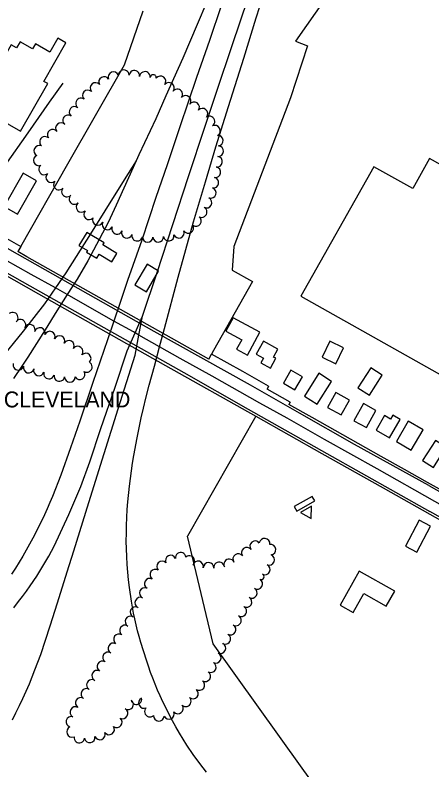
# Model space of a CAD drawing. Extents: x -25029 to 2274964, y -81170 to 687028.
# Drawn here: x -16160 to -15374, y -63645 to -62222 of the extents above; entities that cross this region are included whole.
import ezdxf

# ---------------------------------------------------------------- set-up
doc = ezdxf.new("R2010")
doc.units = 0
for name, color, linetype in [('81911BEA - RW_X_Fee_RW', 7, 'Continuous'), ('BLDG', 7, 'Continuous'), ('CITY-NAME', 7, 'Continuous'), ('GE_X_CL_2000', 7, 'Continuous'), ('ROAD', 7, 'Continuous'), ('TRANSPWRLN', 7, 'Continuous'), ('TREES', 7, 'Continuous')]:
    doc.layers.add(name, color=color, linetype=linetype)

msp = doc.modelspace()

# ---------------------------------------------------------------- linework, layer by layer
at = {"layer": '81911BEA - RW_X_Fee_RW'}
for p, q in [((-15533.2, -62131.6), (-15631, -62271.5)), ((-15954, -62316), (-15918.9, -62214.6)), ((-15631, -62271.5), (-15608.5, -62280.5)), ((-15608.5, -62280.5), (-15640.6, -62378.1)), ((-15640.6, -62378.1), (-15747.6, -62658.6)), ((-16251.2, -62601.3), (-16149.6, -62658.5)), ((-16149.6, -62658.5), (-16155.1, -62668.2)), ((-15747.6, -62658.6), (-15750.9, -62702.9)), ((-16138.1, -62677.7), (-16155.1, -62668.2)), ((-15794.9, -62870.8), (-16138.1, -62677.7)), ((-15750.9, -62702.9), (-15712.5, -62724.4)), ((-15794.9, -62870.8), (-15789.5, -62861.2)), ((-15730.7, -62894.3), (-15789.5, -62861.2)), ((-15681.9, -62921.8), (-15684.8, -62927)), ((-15641.3, -62951.5), (-15684.8, -62927)), ((-15641.3, -62951.5), (-15643.7, -62955.9)), ((-15705.9, -62978.3), (-15835.1, -63204)), ((-15786.7, -63407.4), (-15835.1, -63204))]:
    msp.add_line(p, q, dxfattribs=at)
for points in [[(-16149.6, -62658.5), (-16060.5, -62502.6), (-15954, -62316)], [(-16840.1, -62340.1), (-16798.4, -62363.6), (-16741.8, -62395.4), (-16693.9, -62422.4), (-16645.9, -62449.4), (-16562.7, -62496.2), (-16514.5, -62523.3), (-16429.4, -62571.2), (-16398.8, -62588.4), (-16342.2, -62620.3), (-16307.3, -62639.9), (-16115.8, -62747.6), (-15876.3, -62882.4), (-15705.9, -62978.3)], [(-15712.5, -62724.4), (-15785.7, -62854.4), (-15789.5, -62861.2)], [(-15681.9, -62921.8), (-15691.2, -62916.5), (-15730.7, -62894.3)], [(-15333.3, -63130.6), (-15336.9, -63128.5), (-15382.3, -63103), (-15425.8, -63078.5), (-15469.4, -63054), (-15513, -63029.5), (-15556.6, -63004.9), (-15600.1, -62980.4), (-15643.7, -62955.9)], [(-15705.9, -62978.3), (-15581.3, -63048.4), (-15466.1, -63113.2), (-15353.4, -63176.6), (-15200.7, -63262.5), (-15148.4, -63292), (-15118.6, -63308.8), (-15061.3, -63341), (-15017.3, -63365.7), (-14973.7, -63390.3), (-14930.2, -63414.8), (-14879.6, -63443.2)], [(-15569, -63710.4), (-15570.4, -63708.5), (-15618.7, -63641.2), (-15786.7, -63407.4)]]:
    msp.add_lwpolyline(points, dxfattribs=at)
at = {"layer": 'BLDG'}
for points in [[(-16079.7, -62265.9), (-16094.8, -62292.3), (-16122, -62276.7), (-16127.3, -62286.1), (-16150.7, -62272.7), (-16157.4, -62284.3), (-16167.7, -62278.4), (-16233.5, -62393.4), (-16149.9, -62441.3), (-16098.5, -62351.6), (-16106.1, -62347.3), (-16064.5, -62274.6)], [(-15142.5, -62703.9), (-15122.1, -62715.4), (-15082, -62644.2), (-15171.4, -62594), (-15209.8, -62662.3), (-15310.5, -62605.7), (-15278.5, -62548.8), (-15378.2, -62492.8), (-15410.1, -62549.5), (-15483.8, -62508.1), (-15621, -62752.3), (-15278, -62945)], [(-16145, -62520.5), (-16180.9, -62583.4), (-16155.5, -62597.8), (-16119.7, -62535)], [(-16039.8, -62656.5), (-16023.5, -62666.2), (-16025.4, -62669.4), (-16006.2, -62680.7), (-16001.7, -62673.1), (-15977.5, -62687.5), (-15968, -62671.4), (-15994.7, -62655.6), (-15992.2, -62651.4), (-16025.2, -62631.9)], [(-15934.1, -62730.8), (-15912.2, -62743.6), (-15889.4, -62704.7), (-15911.3, -62691.9)], [(-15762.6, -62817.9), (-15732.7, -62834.1), (-15742.3, -62851.9), (-15721.6, -62863), (-15698.4, -62820), (-15749, -62792.7)], [(-15705.2, -62861.2), (-15691.7, -62868.7), (-15696.7, -62877.7), (-15678.6, -62887.7), (-15668.4, -62869.1), (-15672.6, -62866.8), (-15664.4, -62852.1), (-15691.8, -62837)], [(-15540.7, -62849.7), (-15566.6, -62837.1), (-15581.1, -62867.1), (-15555.3, -62879.6)], [(-15491.6, -62938.5), (-15467.5, -62900.7), (-15489.3, -62886.8), (-15513.4, -62924.6)], [(-15639.8, -62891.2), (-15654.1, -62915.7), (-15632.4, -62928.4), (-15618.1, -62904)], [(-15587.1, -62897.3), (-15614.2, -62940.2), (-15590.2, -62955.4), (-15563.1, -62912.6)], [(-15570.6, -62961.7), (-15545.1, -62975.9), (-15529.6, -62947.9), (-15555.1, -62933.8)], [(-15521, -62986.7), (-15497.5, -62999.7), (-15479.6, -62967.3), (-15503.1, -62954.3)], [(-15433.8, -62984.4), (-15447.7, -62976.3), (-15452.1, -62983.8), (-15463.5, -62977.2), (-15479.4, -63004.3), (-15454, -63019.1)], [(-15441, -63026), (-15413, -63042.3), (-15390.6, -63003.8), (-15418.6, -62987.5)], [(-15391.5, -63061.8), (-15371.1, -63074.7), (-15347.1, -63036.8), (-15367.4, -63023.9)], [(-15628.8, -63156.9), (-15594.8, -63137.8), (-15599.6, -63129.3), (-15633.5, -63148.3)], [(-15402.2, -63234.6), (-15376.7, -63185.6), (-15398.1, -63174.4), (-15423.7, -63223.4)], [(-15444.2, -63307.7), (-15511.3, -63270.1), (-15547.2, -63334.1), (-15522.3, -63348.1), (-15502.3, -63312.4), (-15460.1, -63336.1)]]:
    msp.add_lwpolyline(points, close=True, dxfattribs=at)
at = {"layer": 'GE_X_CL_2000'}
for points in [[(-15919.6, -62789.8), (-15892, -62707.6), (-15833, -62526.5), (-15802.3, -62433.4), (-15779.3, -62364.1), (-15750.7, -62280), (-15720.8, -62190.1), (-15691, -62102.8), (-15685.5, -62086), (-15658.3, -62003.6), (-15618.6, -61883.3), (-15592.4, -61804.9), (-15578.2, -61766.2), (-15548.9, -61700.4), (-15529.9, -61655.6)], [(-15733.4, -62049.1), (-15741.8, -62066.3), (-15750.9, -62085.5), (-15758, -62101.1), (-15765.7, -62118.6), (-15773.2, -62136.2), (-15780.5, -62153.9), (-15816.9, -62240.2), (-15844, -62303.4), (-15875.6, -62374.5), (-15894.8, -62418), (-15926.6, -62485.7), (-15931.9, -62496.9)], [(-15799.4, -63649.2), (-15811.8, -63632.4), (-15824, -63615.5), (-15836.2, -63598.2), (-15843.3, -63586.7), (-15850.2, -63575.2), (-15856.8, -63563.7), (-15863.3, -63552), (-15869.5, -63540.3), (-15875.5, -63528.4), (-15881.3, -63516.4), (-15886.4, -63505.4), (-15891.3, -63494.4), (-15895.9, -63483.3), (-15900.4, -63472.1), (-15904.7, -63460.9), (-15908.7, -63449.5), (-15912.6, -63438.1), (-15923, -63404.6), (-15926.3, -63393.6), (-15929.3, -63382.6), (-15932.1, -63371.5), (-15934.6, -63360.3), (-15936.9, -63349.1), (-15939, -63337.9), (-15940.8, -63326.6), (-15944.4, -63300.9), (-15946, -63286.5), (-15947.4, -63271.9), (-15948.5, -63257.4), (-15949.4, -63242.8), (-15950, -63228.2), (-15950.4, -63213.6), (-15950.3, -63198.7), (-15949.9, -63183.9), (-15949.3, -63169.1), (-15948.5, -63154.3), (-15947.4, -63139.5), (-15944.5, -63110.2), (-15942.7, -63095.7), (-15940.8, -63081.2), (-15938.5, -63066.7), (-15936.1, -63052.2), (-15930, -63019.1), (-15926.2, -63000.3), (-15922.2, -62981.5), (-15918, -62962.8), (-15913.5, -62944), (-15907, -62919.8), (-15897.3, -62883.7), (-15887.8, -62847.4), (-15878.7, -62812.8), (-15852.6, -62716), (-15823.4, -62611.8), (-15800.8, -62536.9), (-15781.4, -62471), (-15757.9, -62394.8), (-15728.6, -62303.4), (-15705.5, -62227.8), (-15691.7, -62184.2)], [(-15771.3, -62204.8), (-15793.4, -62270.3), (-15817.8, -62339.8), (-15849.4, -62433.3), (-15873.3, -62504.8), (-15894.7, -62566), (-15921.4, -62646.3), (-15948, -62722.5), (-15962.5, -62765.6), (-15973.7, -62798.9), (-15985.6, -62834.2), (-16013.4, -62914.9), (-16038.1, -62987.7), (-16055.5, -63037.9), (-16074, -63089.3), (-16089.9, -63129.5), (-16094.6, -63141.1), (-16099.5, -63152.5), (-16104.6, -63163.8), (-16115.3, -63186.2), (-16126.7, -63208.3), (-16139.2, -63230.8), (-16145.8, -63242.2), (-16152.6, -63253.5), (-16159.6, -63264.6), (-16166.8, -63275.7)], [(-16070.2, -62351), (-16096.1, -62386.3), (-16136.4, -62444.3), (-16179.3, -62506), (-16209.7, -62547.7), (-16242.7, -62590.6), (-16269, -62632.7)], [(-15931.9, -62496.9), (-15954.2, -62532.7), (-15991.1, -62591.2), (-16018.2, -62634.9), (-16064.6, -62708.1), (-16084.3, -62736.5), (-16105, -62766.3), (-16145.1, -62818.3), (-16191.6, -62874.6)], [(-15931.9, -62496.9), (-15969.4, -62580.8), (-15984.5, -62613.1), (-16022.8, -62685.3), (-16043.4, -62720.2), (-16061.9, -62749.1), (-16061.9, -62749.2), (-16081.5, -62779.9), (-16103.7, -62815.3), (-16136.2, -62866.8), (-16147.7, -62884.2), (-16163.1, -62907.3)], [(-15181.3, -63244.5), (-15264.3, -63197.2), (-15345.1, -63152.2), (-15368.3, -63139.2), (-15477.3, -63077.7), (-15576.6, -63022), (-15647.3, -62982.2), (-15698.4, -62953.4), (-15788.2, -62903), (-15848.7, -62869.6), (-15887.8, -62847.4), (-15926.5, -62825.4), (-15933.7, -62821.3), (-15937.1, -62819.4), (-15973.7, -62798.9), (-16010.3, -62778.4), (-16061.9, -62749.1), (-16075, -62741.7), (-16084.3, -62736.5), (-16129.9, -62711), (-16178.7, -62683.6), (-16240.2, -62648.9), (-16269, -62632.7)], [(-16165.3, -63550.2), (-16158.6, -63537), (-16152, -63523.6), (-16145.7, -63510.1), (-16133.3, -63482.6), (-16123.1, -63456.3), (-16111.8, -63427), (-16094, -63373), (-16080.2, -63330.2), (-16062.2, -63271.2), (-16049.2, -63232), (-16021.2, -63141.1), (-15992.5, -63048.7), (-15965.8, -62964.6), (-15933.8, -62863.1), (-15926.5, -62825.4), (-15919.6, -62789.8)], [(-16162.7, -63339), (-16153.6, -63327.6), (-16146.1, -63317.8), (-16138.7, -63307.9), (-16131.5, -63297.9), (-16119.5, -63279.4), (-16107.7, -63260.8), (-16096.3, -63241.9), (-16086.5, -63223), (-16058.6, -63163.4), (-16036.4, -63110.4), (-16019.3, -63063.9), (-15998.2, -63001.7), (-15971.4, -62923.3), (-15948.7, -62854.8), (-15933.7, -62821.3), (-15919.6, -62789.8)]]:
    msp.add_lwpolyline(points, dxfattribs=at)
at = {"layer": 'ROAD'}
for points in [[(-15379.5, -63109.1), (-15251.1, -63181.4), (-15199.1, -63209.6), (-15189.1, -63209.8), (-15174.4, -63204.9), (-15169.3, -63201.6), (-15165.9, -63198.6), (-15163.2, -63194.3), (-15113.8, -63102.4), (-15104.4, -63081.1), (-15092.6, -63049), (-15082.2, -63014.2), (-15075.9, -62987.7), (-15069.7, -62952.5), (-15057.6, -62885.1), (-15043.7, -62802.8), (-15019.2, -62663.5), (-14993, -62505.8), (-14969.6, -62367.9), (-14939.6, -62190.8)], [(-15379.5, -63109.1), (-15520.2, -63031.4), (-15623.8, -62972.5), (-15716.4, -62919.9), (-15897.8, -62818.5), (-16103.2, -62702.7), (-16246.3, -62622)], [(-16290.8, -62643.4), (-16132.6, -62732.4), (-15982.9, -62816.8), (-15841.9, -62895.7), (-15720.4, -62964.8), (-15572, -63048.5), (-15377.7, -63157.9)], [(-14748.4, -63511.5), (-14840.2, -63460), (-14955, -63395.7), (-15043.4, -63345.9), (-15125.3, -63300.4), (-15224.8, -63243.6), (-15335, -63181.8), (-15377.7, -63157.9)]]:
    msp.add_lwpolyline(points, dxfattribs=at)
at = {"layer": 'TRANSPWRLN'}
msp.add_lwpolyline([(-15601.6, -63170.9), (-15601.1, -63147.5), (-15622.1, -63159.4)], close=True, dxfattribs=at)
at = {"layer": 'TREES'}
for centre, radius, start, end in [((-15974.5, -62339.5), 10, 22.219, 202.219), ((-15955.3, -62335.8), 10, 359.3189, 179.3189), ((-15935.3, -62336.9), 10, 354.1543, 174.1543), ((-15915.4, -62339), 10, 354.1543, 174.1543), ((-15899.7, -62340.6), 5.86, 354.1543, 174.1543), ((-15992.4, -62348.4), 10, 30.749, 210.749), ((-15885.9, -62347.3), 10, 322.4583, 142.4583), ((-15870, -62359.5), 10, 322.3905, 142.3905), ((-16023.1, -62373.7), 10, 47.2934, 227.2934), ((-16008.6, -62359.9), 10, 39.9339, 219.9339), ((-15854.2, -62371.7), 10, 321.9677, 141.9677), ((-15838.5, -62384.1), 10, 321.6468, 141.6468), ((-16035.9, -62389), 10, 52.9647, 232.9647), ((-15822.5, -62396.1), 10, 324.9022, 144.9022), ((-16048.1, -62404.9), 10, 52.0162, 232.0162), ((-15806.7, -62408.3), 10, 319.7181, 139.7181), ((-16060.3, -62420.7), 10, 52.5748, 232.5748), ((-15793.5, -62423), 10, 304.1006, 124.1006), ((-16073.8, -62435.3), 10, 41.7584, 221.7584), ((-15783.2, -62440.2), 10, 297.648, 117.648), ((-16089.4, -62447.8), 10, 36.0466, 216.0466), ((-15777.7, -62459), 10, 275.2833, 95.2833), ((-16103.9, -62461.4), 10, 49.9203, 229.9203), ((-16114.8, -62478), 10, 63.6893, 243.6893), ((-15777.2, -62478.9), 10, 267.1377, 87.1377), ((-16115.5, -62496.2), 10, 111.8266, 291.8266), ((-15779.2, -62498.8), 10, 261.6699, 81.6699), ((-16105.4, -62513.2), 10, 129.603, 309.603), ((-15782.4, -62518.5), 10, 259.6963, 79.6963), ((-16092.1, -62528.1), 10, 133.8231, 313.8231), ((-15786.1, -62538.2), 10, 258.9064, 78.9064), ((-16077.6, -62541.9), 10, 139.247, 319.247), ((-16062.5, -62555), 10, 138.4171, 318.4171), ((-15791.2, -62557.5), 10, 251.4076, 71.4076), ((-16048.3, -62569), 10, 132.5792, 312.5792), ((-16034.9, -62583.8), 10, 131.9559, 311.9559), ((-15799.1, -62575.8), 10, 242.3694, 62.3694), ((-16020.7, -62597.9), 10, 138.1491, 318.1491), ((-15808.3, -62593.6), 10, 242.7847, 62.7847), ((-16004.1, -62608.5), 10, 157.0549, 337.0549), ((-15818.9, -62610.4), 10, 232.9135, 52.9135), ((-15985.9, -62616.8), 10, 154.0795, 334.0795), ((-15833.4, -62623.6), 10, 211.4356, 31.4356), ((-15967.7, -62625.2), 10, 156.1471, 336.1471), ((-15949.2, -62632.7), 10, 159.7091, 339.7091), ((-15851.3, -62632.6), 10, 201.9454, 21.9454), ((-15930, -62638.1), 10, 168.8014, 348.8014), ((-15910.2, -62640.5), 10, 177.6309, 357.6309), ((-15890.2, -62640.3), 10, 183.5325, 3.5325), ((-15870.4, -62638), 10, 189.5995, 9.5995), ((-16164.6, -62792.6), 10, 310.4833, 130.4833), ((-16150.1, -62806.1), 10, 323.9145, 143.9145), ((-16132.6, -62815.3), 10, 340.4267, 160.4267), ((-16113.5, -62821.5), 10, 343.5881, 163.5881), ((-16094.8, -62828.3), 10, 336.4427, 156.4427), ((-16076.6, -62836.6), 10, 334.6327, 154.6327), ((-16058.7, -62845.6), 10, 331.5935, 151.5935), ((-16042.1, -62856.5), 10, 322.1271, 142.1271), ((-16027, -62869.7), 10, 315.5091, 135.5091), ((-16154, -62881.4), 10, 164.439, 344.439), ((-16134.7, -62886.6), 10, 165.3073, 345.3073), ((-16115.4, -62892.1), 10, 163.0326, 343.0326), ((-16024.8, -62885.3), 10, 240.3181, 60.3181), ((-16096.3, -62897.8), 10, 163.4698, 343.4698), ((-16076.8, -62902.4), 10, 170.052, 350.052), ((-16057, -62904.2), 10, 179.5209, 359.5209), ((-16038.4, -62899.2), 10, 210.817, 30.817), ((-15707.4, -63223.3), 10, 37.8672, 217.8672), ((-15689.6, -63218.4), 10, 352.6104, 172.6104), ((-15723.2, -63235.5), 10, 37.0491, 217.0491), ((-15678.4, -63229.7), 10, 277.0624, 97.0624), ((-15866.8, -63250.3), 10, 23.7539, 203.7539), ((-15847.8, -63245), 10, 7.4754, 187.4754), ((-15831.3, -63251.2), 10, 311.2611, 131.2611), ((-15739.4, -63247.3), 10, 35.3353, 215.3353), ((-15681, -63248.8), 10, 247.5897, 67.5897), ((-15883, -63261.5), 10, 45.1866, 225.1866), ((-15815, -63261.2), 10, 345.6797, 165.6797), ((-15795.3, -63264.1), 10, 357.8726, 177.8726), ((-15775.4, -63263.2), 10, 7.1647, 187.1647), ((-15756.5, -63257.5), 10, 26.3951, 206.3951), ((-15689.1, -63267.1), 10, 244.2789, 64.2789), ((-15895.8, -63276.8), 10, 55.2599, 235.2599), ((-15906.4, -63293.7), 10, 60.5157, 240.5157), ((-15703.3, -63294.1), 10, 238.3281, 58.3281), ((-15695.8, -63280.8), 5.25, 244.2789, 64.2789), ((-15915.6, -63311.4), 10, 64.7074, 244.7074), ((-15713.7, -63311.2), 10, 239.1511, 59.1511), ((-15924.1, -63329.5), 10, 64.8135, 244.8135), ((-15723.7, -63328.4), 10, 240.3636, 60.3636), ((-15933.1, -63347.4), 10, 62.0058, 242.0058), ((-15733.6, -63345.8), 10, 240.3772, 60.3772), ((-15942.6, -63365), 10, 61.0708, 241.0708), ((-15743.7, -63363.1), 10, 239.3096, 59.3096), ((-15953.1, -63382), 10, 55.4978, 235.4978), ((-15753.8, -63380.3), 10, 239.6947, 59.6947), ((-15964.4, -63398.5), 10, 56.0099, 236.0099), ((-15763.8, -63397.7), 10, 240.6788, 60.6788), ((-15974.8, -63415.6), 10, 61.2006, 241.2006), ((-15772.9, -63415.5), 10, 244.8764, 64.8764), ((-15984.9, -63432.8), 10, 57.7793, 237.7793), ((-15781.7, -63433.4), 10, 243.1735, 63.1735), ((-15995.5, -63449.8), 10, 58.5358, 238.5358), ((-15791.1, -63451.1), 10, 240.4073, 60.4073), ((-16005.4, -63467.1), 10, 62.0022, 242.0022), ((-15801.5, -63468.2), 10, 237.4113, 57.4113), ((-16015.3, -63484.5), 10, 58.2253, 238.2253), ((-15812.6, -63484.8), 10, 234.8051, 54.8051), ((-16025.9, -63501.4), 10, 57.784, 237.784), ((-15824.7, -63500.7), 10, 230.4927, 50.4927), ((-16036.5, -63518.4), 10, 58.4298, 238.4298), ((-15947, -63521.2), 10, 234.7814, 54.7814), ((-15931.4, -63511.3), 10, 190.1327, 10.1327), ((-15917.2, -63518.6), 10, 115.7662, 295.7662), ((-15838.1, -63515.5), 10, 225.7556, 45.7556), ((-16046.5, -63535.7), 10, 61.3575, 241.3575), ((-15957.4, -63538.3), 10, 242.2812, 62.2812), ((-15906, -63534.8), 10, 133.6154, 313.6154), ((-15852.9, -63528.9), 10, 218.0068, 38.0068), ((-16054, -63554.1), 10, 74.4329, 254.4329), ((-15889.1, -63542.6), 10, 176.9025, 356.9025), ((-15869.9, -63539.1), 10, 203.8935, 23.8935), ((-15968.3, -63554.9), 10, 231.177, 51.177), ((-16052.9, -63573), 10, 112.5566, 292.5566), ((-15982.8, -63568.5), 10, 215.4667, 35.4667), ((-16039.1, -63583.7), 10, 171.8116, 351.8116), ((-16019.4, -63583.3), 10, 190.2563, 10.2563), ((-16000.2, -63577.9), 10, 201.1463, 21.1463)]:
    msp.add_arc(centre, radius, start, end, dxfattribs=at)

# ---------------------------------------------------------------- texts
at = {"layer": 'CITY-NAME'}
msp.add_text('CLEVELAND', height=30, dxfattribs=at).set_placement((-16181.4, -62961.7))

doc.saveas('drawing.dxf')
